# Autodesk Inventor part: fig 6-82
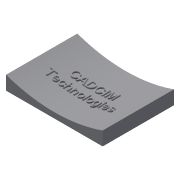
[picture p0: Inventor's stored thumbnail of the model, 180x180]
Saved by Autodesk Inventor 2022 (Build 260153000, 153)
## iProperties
Part Number: fig 6-82
Document SubType Name: Modeling
Created: 2002-12
Designer: deepak
Density: 1 g/cm^3
Material: Generic
Appearance: Default
Control State: 0
Master: False
Checked Out: False
Shininess: 64.0
Length Units: 11269
Angle Units: 11279
Time Units: 11290
Mass Units: 11283
Length Display Precision: 3
Angle Display Precision: 2
Compacted: True
Density: 0.0
Volumn: 0.0
Area: 0.0
PropertySet Name: Model Information
Author: deepak
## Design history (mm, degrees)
sketch "Sketch1"
  geometry: L1 (-39.922, 33.786)-(30.103, 33.786); L2 (30.103, 33.786)-(30.103, -17.894); L3 (30.103, -17.894)-(-39.922, -17.894); L4 (-39.922, -17.894)-(-39.922, 33.786)
  constraints: 8 end point, 2 parallel, 1 horizontal, 1 perpendicular
extrude "Extrusion1" new body sketch "Sketch1" distance "d0" = 10; taper "d1" = 0 deg
workplane "Work Plane1"
sketch "Sketch2"
  geometry: L1 (-37.656, 15.034)-(26.28, 15.034); L2 (26.28, 15.034)-(26.28, 10.168); L3 (26.28, 10.168)-(-37.656, 10.168); L4 (-37.656, 10.168)-(-37.656, 15.034)
  constraints: 2 other
sketch "Sketch3"
  geometry: L1 (70.026, 10)-(0, 10) reference; A1 r 105 centre (35.013, 108.99) between (0, 10) and (70.026, 10)
  constraints: 2 point on circle, 1 centre point
  dimensions: "d5" = 105 radius of A1
extrude "Extrusion2" cut sketch "Sketch3" extent not by distance; stored distance "d3" = 10; taper "d4" = 0 deg
emboss "Emboss4" sketch "Sketch2" dims "d14" = 1, "d15" = 0
body "Solid1"
other parameters: "d2" = 5
